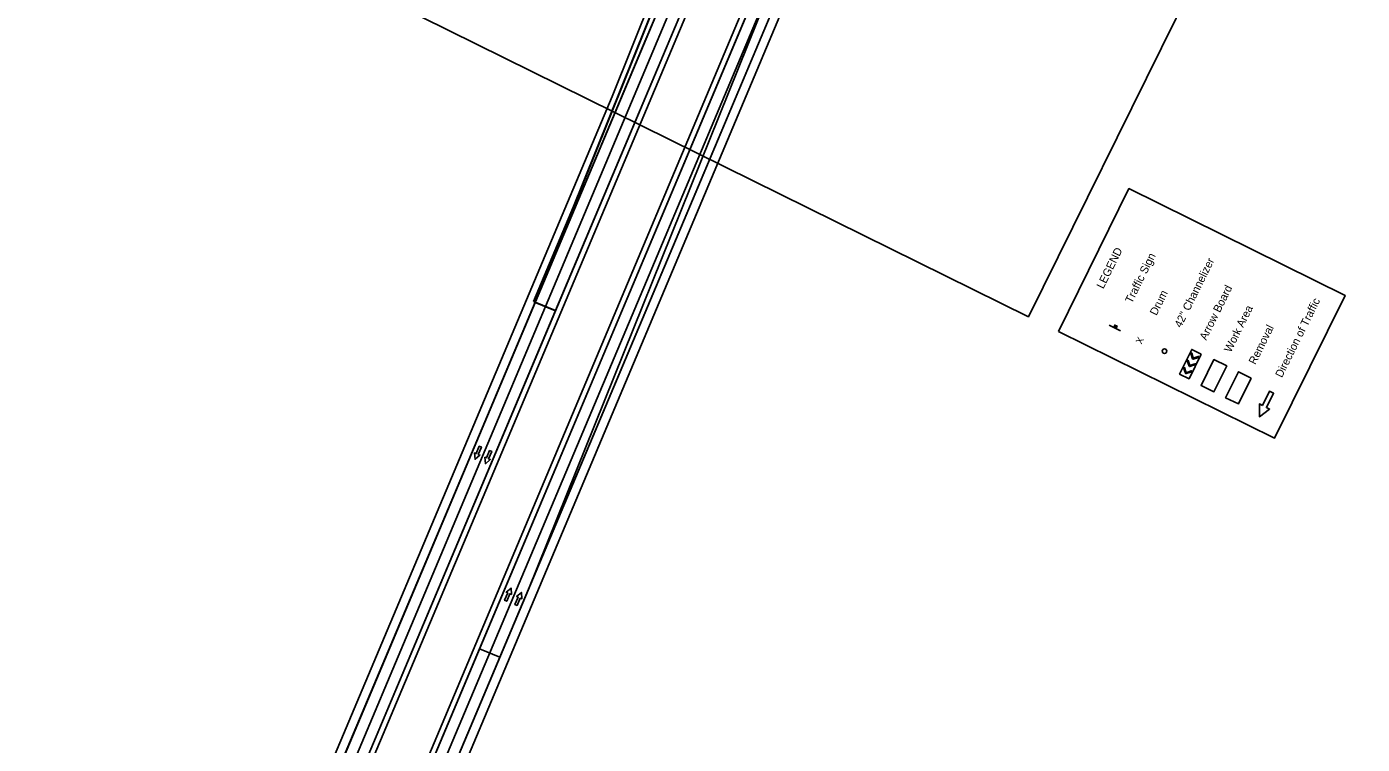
# Model space of a CAD drawing. Extents: x 14097936 to 14128734, y 8632000 to 8683104.
# Drawn here: x 14117857 to 14119318, y 8666961 to 8667745 of the extents above; entities that cross this region are included whole.
import ezdxf

# ---------------------------------------------------------------- set-up
doc = ezdxf.new("R2010")
doc.units = 0
for name, color, linetype in [('dsn_stg_shd_prev', 7, 'Continuous'), ('dsnNonPlotable', 7, 'Continuous'), ('dsnPaintExistingBrokenLaneLineWhite', 7, 'Continuous'), ('dsnPaintExistingEdgeLineLeftYellow', 7, 'Continuous'), ('dsnPaintExistingEdgeLineRightWhite', 7, 'Continuous'), ('dsnPaintPlaceBrokenLaneWhite', 7, 'Continuous'), ('dsnPaintPlaceEdgeLineRightWhite', 7, 'Continuous'), ('dsnShadingPaved', 7, 'Continuous'), ('dsnStgShadingPrevPav', 7, 'Continuous'), ('dsnTapeRemoveChannelizingLaneWhite', 7, 'Continuous'), ('dsnTextOverlapEven', 7, 'Continuous'), ('Level 2', 7, 'Continuous'), ('Level 5', 7, 'Continuous')]:
    doc.layers.add(name, color=color, linetype=linetype)

msp = doc.modelspace()

# ---------------------------------------------------------------- linework, layer by layer
at = {"layer": 'dsn_stg_shd_prev'}
for p, q in [((14118497.2, 8667669.3), (14118638, 8668019.9)), ((14115815.8, 8661214.6), (14118674.8, 8668003.7)), ((14115815.8, 8661214.6), (14118674.8, 8668003.7)), ((14118680.7, 8668002), (14115821.7, 8661212.9)), ((14118652.6, 8668013.1), (14118415.9, 8667450.9)), ((14118652.6, 8668013.1), (14118415.9, 8667450.9)), ((14110809.2, 8649413), (14118497.2, 8667669.3)), ((14118415.9, 8667450.9), (14110818, 8649408.6)), ((14118415.9, 8667450.9), (14110818, 8649408.6))]:
    msp.add_line(p, q, dxfattribs=at)
at = {"layer": 'dsnNonPlotable'}
msp.add_lwpolyline([(14118047.2, 8667875.9), (14118741.9, 8669281), (14119647.3, 8668833.4), (14118952.6, 8667428.2)], close=True, dxfattribs=at)
at = {"layer": 'dsnPaintExistingBrokenLaneLineWhite'}
for p, q in [((14118664.1, 8668009), (14118424.3, 8667439.6)), ((14114932.5, 8658913.4), (14118537.6, 8667474.2)), ((14114932.5, 8658913.4), (14118537.6, 8667474.2)), ((14110829.5, 8649404.5), (14118424.3, 8667439.6))]:
    msp.add_line(p, q, dxfattribs=at)
at = {"layer": 'dsnPaintExistingEdgeLineLeftYellow'}
for p, q in [((14115900.9, 8661244), (14118759.4, 8668031.7)), ((14118675.1, 8668004.3), (14118435.4, 8667434.9)), ((14118435.4, 8667434.9), (14115816.1, 8661215.2))]:
    msp.add_line(p, q, dxfattribs=at)
at = {"layer": 'dsnPaintExistingEdgeLineRightWhite'}
for p, q in [((14110924.4, 8649364.5), (14118874.7, 8668243.7)), ((14118643.5, 8668017.6), (14118412.9, 8667444.4)), ((14118413.2, 8667444.3), (14115798.8, 8661235.7))]:
    msp.add_line(p, q, dxfattribs=at)
at = {"layer": 'dsnPaintPlaceBrokenLaneWhite'}
msp.add_line((14118537.6, 8667474.2), (14118951.7, 8668457.6), dxfattribs=at)
at = {"layer": 'dsnPaintPlaceEdgeLineRightWhite'}
msp.add_line((14118413.2, 8667444.3), (14110818.4, 8649409.2), dxfattribs=at)
at = {"layer": 'dsnShadingPaved'}
for p, q in [((14118937.1, 8668391.9), (14118374.4, 8667055.7)), ((14118352.3, 8667065), (14118824.8, 8668187.1)), ((14118413.2, 8667444.3), (14118643.5, 8668017.6)), ((14118413.2, 8667444.3), (14118576.7, 8667832.4)), ((14118576.7, 8667832.4), (14118534.2, 8667731.7)), ((14118598.8, 8667823.1), (14118435.4, 8667434.9)), ((14118534.2, 8667731.7), (14118413, 8667443.7)), ((14110818.4, 8649409.2), (14118413.2, 8667444.3)), ((14118413.2, 8667444.3), (14118435.4, 8667434.9)), ((14118435.4, 8667434.9), (14118413.2, 8667444.3)), ((14118435.4, 8667434.9), (14110840.5, 8649399.8)), ((14116702.8, 8663382.6), (14118413, 8667443.7)), ((14118435.2, 8667434.6), (14116725, 8663373.3)), ((14118413, 8667443.7), (14118435.2, 8667434.6)), ((14118374.4, 8667055.7), (14118352.3, 8667065))]:
    msp.add_line(p, q, dxfattribs=at)
msp.add_lwpolyline([(14118352.3, 8667065), (14117996.2, 8666219.5), (14117609.5, 8665301.3), (14116829, 8663447.7), (14116851.1, 8663438.4), (14116956.9, 8663689.5), (14117040.3, 8663887.7), (14117116, 8664067.4), (14117232.4, 8664343.9), (14117405.1, 8664754), (14117547.8, 8665092.7), (14117686.5, 8665422.2), (14117866, 8665848.4), (14118096, 8666394.5), (14118374.4, 8667055.7)], close=True, dxfattribs=at)
at = {"layer": 'dsnStgShadingPrevPav'}
for p, q in [((14115895.6, 8661246.8), (14118811.5, 8668171)), ((14118848.4, 8668155.5), (14115932.5, 8661231.3)), ((14118643.5, 8668017.6), (14118458, 8667555.6)), ((14118458.1, 8667555.6), (14118643.6, 8668017.6)), ((14118497.2, 8667669.3), (14118638, 8668019.9)), ((14115816.1, 8661215.2), (14118675.1, 8668004.3)), ((14115816.1, 8661215.2), (14118675.1, 8668004.3)), ((14118680.7, 8668002), (14115821.7, 8661212.9)), ((14118652.8, 8668013), (14118416, 8667450.8)), ((14118653, 8668013.6), (14118416.3, 8667451.4)), ((14110809.2, 8649413), (14118497.2, 8667669.3)), ((14118458, 8667555.6), (14118411.4, 8667445)), ((14118411.5, 8667445), (14118458.1, 8667555.6)), ((14118416.3, 8667451.4), (14110818.4, 8649409.2)), ((14118413.2, 8667444.3), (14110818.4, 8649409.2)), ((14118411.4, 8667445), (14118413.2, 8667444.3)), ((14118413.4, 8667444.2), (14118411.5, 8667445)), ((14118416, 8667450.8), (14118413.2, 8667444.3))]:
    msp.add_line(p, q, dxfattribs=at)
at = {"layer": 'dsnTapeRemoveChannelizingLaneWhite'}
msp.add_line((14118693.2, 8667843.6), (14118405.4, 8667129.3), dxfattribs=at)
at = {"layer": 'dsnTextOverlapEven'}
for p, q in [((14119040.9, 8667418.9), (14119053.2, 8667412.9)), ((14119045.9, 8667416.9), (14119048.4, 8667415.6)), ((14119048.4, 8667415.5), (14119045.9, 8667416.7)), ((14119048.5, 8667415.7), (14119046, 8667417)), ((14119048.6, 8667415.9), (14119046.1, 8667417.2)), ((14119046.1, 8667417.1), (14119048.6, 8667415.8)), ((14119048.7, 8667416.2), (14119046.2, 8667417.4)), ((14119046.2, 8667417.3), (14119048.7, 8667416)), ((14119048.8, 8667416.4), (14119046.3, 8667417.6)), ((14119046.3, 8667417.5), (14119048.8, 8667416.3)), ((14119046.4, 8667417.8), (14119048.9, 8667416.6)), ((14119049, 8667416.7), (14119046.5, 8667418)), ((14119046.6, 8667418.2), (14119049.1, 8667416.9)), ((14119049.1, 8667417), (14119046.6, 8667418.2)), ((14119046.7, 8667418.4), (14119049.2, 8667417.2)), ((14119046.8, 8667418.7), (14119049.3, 8667417.4)), ((14119049.3, 8667417.3), (14119046.8, 8667418.5)), ((14119049.4, 8667417.5), (14119046.9, 8667418.8)), ((14119047, 8667418.9), (14119049.5, 8667417.7)), ((14119128.9, 8667373.9), (14119134.8, 8667375.9)), ((14119132.8, 8667381.8), (14119138.7, 8667383.8)), ((14119125, 8667366), (14119130.9, 8667368))]:
    msp.add_line(p, q, dxfattribs=at)
for points in [[(14118985.3, 8667412.1), (14119062.5, 8667568.4), (14119298.8, 8667451.6), (14119221.5, 8667295.3)], [(14118985.3, 8667412.1), (14119062.5, 8667568.4), (14119298.8, 8667451.6), (14119221.5, 8667295.3)], [(14119048.3, 8667415.3), (14119045.8, 8667416.6), (14119047, 8667419.1), (14119049.6, 8667417.9)], [(14119141.5, 8667387.3), (14119128.2, 8667360.4), (14119117.9, 8667365.5), (14119131.2, 8667392.4)], [(14119169.4, 8667374.4), (14119155.4, 8667381.4), (14119141.4, 8667353), (14119155.4, 8667346.1)], [(14119141.4, 8667353), (14119155.4, 8667381.4), (14119169.4, 8667374.4), (14119155.4, 8667346.1)], [(14119196.3, 8667361.1), (14119182.3, 8667368.1), (14119168.2, 8667339.7), (14119182.3, 8667332.8)], [(14119196.3, 8667361.1), (14119182.3, 8667368.1), (14119168.2, 8667339.7), (14119182.3, 8667332.8)]]:
    msp.add_lwpolyline(points, close=True, dxfattribs=at)
for points in [[(14119130.1, 8667388.1), (14119130.1, 8667388), (14119132.1, 8667382.1), (14119132.1, 8667382.1)], [(14119138.4, 8667384.8), (14119138.3, 8667384.8), (14119132.9, 8667382.8), (14119131.1, 8667388.4)], [(14119122.3, 8667372.3), (14119122.3, 8667372.3), (14119124.3, 8667366.4), (14119124.3, 8667366.4)], [(14119130.6, 8667369), (14119130.5, 8667369), (14119125.1, 8667367), (14119123.3, 8667372.6)], [(14119126.2, 8667380.1), (14119126.2, 8667380.1), (14119128.2, 8667374.2), (14119128.2, 8667374.2)], [(14119134.5, 8667376.9), (14119134.4, 8667376.9), (14119128.9, 8667374.8), (14119127.2, 8667380.4)], [(14119208.4, 8667331.1), (14119205.1, 8667332.8), (14119205.1, 8667318.8), (14119216.3, 8667327.3), (14119212.9, 8667328.9), (14119220.7, 8667344.6), (14119216.2, 8667346.8), (14119208.4, 8667331.1)]]:
    msp.add_lwpolyline(points, dxfattribs=at)
msp.add_circle((14119101.4, 8667390.6), 2.5, dxfattribs=at)
msp.add_circle((14119101.4, 8667390.6), 2.5, dxfattribs=at)
for centre, start, end in [((14119130.6, 8667388.2), 16.331, 197.4902), ((14119122.8, 8667372.4), 16.331, 197.4902), ((14119126.7, 8667380.3), 16.331, 197.4902), ((14119128.7, 8667374.4), 199.0813, 289.5296), ((14119132.6, 8667382.3), 199.0813, 289.5296), ((14119134.6, 8667376.4), 288.4101, 108.5937), ((14119138.5, 8667384.3), 288.4101, 108.5937), ((14119124.8, 8667366.5), 199.0813, 289.5296), ((14119130.7, 8667368.5), 288.4101, 108.5937)]:
    msp.add_arc(centre, 0.515, start, end, dxfattribs=at)
at = {"layer": 'Level 2'}
for points in [[(14118354.3, 8667285.6), (14118352, 8667286.6), (14118348.6, 8667278.5), (14118346.8, 8667279.3), (14118347.3, 8667272.3), (14118352.6, 8667276.9), (14118350.9, 8667277.6)], [(14118365.5, 8667280.9), (14118363.2, 8667281.9), (14118359.8, 8667273.8), (14118358.1, 8667274.5), (14118358.6, 8667267.5), (14118363.9, 8667272.1), (14118362.2, 8667272.8)], [(14118379.7, 8667118.1), (14118382, 8667117.1), (14118385.4, 8667125.2), (14118387.1, 8667124.5), (14118386.7, 8667131.4), (14118381.4, 8667126.9), (14118383.1, 8667126.2)], [(14118391, 8667113.3), (14118393.3, 8667112.4), (14118396.7, 8667120.4), (14118398.5, 8667119.7), (14118398, 8667126.7), (14118392.7, 8667122.1), (14118394.4, 8667121.4)]]:
    msp.add_lwpolyline(points, close=True, dxfattribs=at)
at = {"layer": 'Level 5'}
for points in [[(14118350.9, 8667277.6), (14118352.6, 8667276.9), (14118347.3, 8667272.3), (14118346.8, 8667279.3), (14118348.6, 8667278.5), (14118352, 8667286.6), (14118354.3, 8667285.6), (14118350.9, 8667277.6)], [(14118362.2, 8667272.8), (14118363.9, 8667272.1), (14118358.6, 8667267.5), (14118358.1, 8667274.5), (14118359.8, 8667273.8), (14118363.2, 8667281.9), (14118365.5, 8667280.9), (14118362.2, 8667272.8)], [(14118383.1, 8667126.2), (14118381.4, 8667126.9), (14118386.7, 8667131.4), (14118387.1, 8667124.5), (14118385.4, 8667125.2), (14118382, 8667117.1), (14118379.7, 8667118.1), (14118383.1, 8667126.2)], [(14118394.4, 8667121.4), (14118392.7, 8667122.1), (14118398, 8667126.7), (14118398.5, 8667119.7), (14118396.7, 8667120.4), (14118393.3, 8667112.4), (14118391, 8667113.3), (14118394.4, 8667121.4)]]:
    msp.add_lwpolyline(points, dxfattribs=at)

# ---------------------------------------------------------------- texts
at = {"layer": 'dsnTextOverlapEven'}
for s, height, p in [('LEGEND', 8.75, (14119034.4, 8667458.1)), ('Traffic Sign', 8.75, (14119065.7, 8667442.2)), ('42" Channelizer ', 8.75, (14119119.5, 8667415.6)), ('Arrow Board', 8.75, (14119147, 8667401.8)), ('Drum', 8.75, (14119092.6, 8667428.9)), ('Direction of Traffic', 8.75, (14119229.8, 8667360.9)), ('Work Area', 8.75, (14119173.9, 8667388.5)), ('Removal', 8.75, (14119200.8, 8667375.2)), ('X', 7.5, (14119076.2, 8667397.6))]:
    msp.add_text(s, height=height, rotation=63.6912, dxfattribs=at).set_placement(p)

doc.saveas('drawing.dxf')
